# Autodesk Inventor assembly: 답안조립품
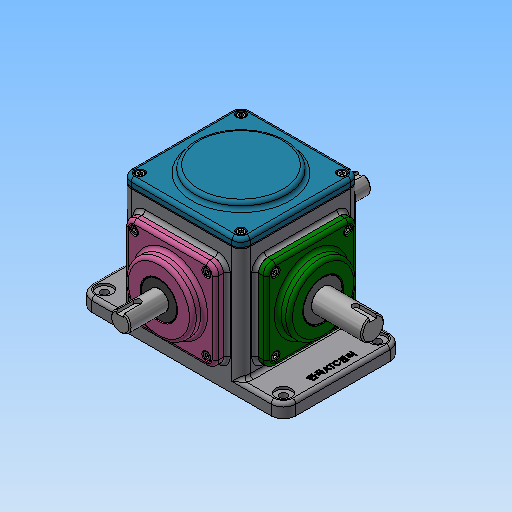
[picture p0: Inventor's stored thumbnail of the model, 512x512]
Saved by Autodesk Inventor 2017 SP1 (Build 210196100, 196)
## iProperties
Part Number: 답안조립품
Material: 일반
Document SubType Name: Assembly
Designer: MRC
Author: MRC
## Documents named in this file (20)
- C:\Users\MRC\Desktop\620307V1005\답안조립품.iam
- C:\Users\MRC\Desktop\620307V1005\본체.ipt
- C:\Users\MRC\Desktop\620307V1005\개스킷.ipt
- C:\Users\MRC\Desktop\620307V1005\메인베벨기어.ipt
- C:\Users\MRC\Desktop\620307V1005\메인축.ipt
- C:\Users\MRC\Desktop\620307V1005\메인커버.ipt
- C:\Users\MRC\Desktop\620307V1005\베어링 6203.ipt
- C:\Users\MRC\Desktop\620307V1005\베어링 6204.ipt
- C:\Users\MRC\Desktop\620307V1005\볼트 M4.ipt
- C:\Users\MRC\Desktop\620307V1005\상부커버.ipt
- C:\Users\MRC\Desktop\620307V1005\서브베벨기어.ipt
- C:\Users\MRC\Desktop\620307V1005\서브축.ipt
- C:\Users\MRC\Desktop\620307V1005\서브커버.ipt
- C:\Users\MRC\Desktop\620307V1005\오일 실 17 32 8.ipt
- C:\Users\MRC\Desktop\620307V1005\오일 실 20 35 8.ipt
- C:\Users\MRC\Desktop\620307V1005\키 4x4.ipt
- C:\Users\MRC\Desktop\620307V1005\서브베벨기어_MIR.ipt
- C:\Users\MRC\Desktop\620307V1005\서브축_MIR.ipt
- C:\Users\MRC\Desktop\620307V1005\서브커버_MIR.ipt
- C:\Users\MRC\Desktop\620307V1005\키 4x4_MIR.ipt
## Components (1 placed, 1 different names)
1. 개스킷:1
